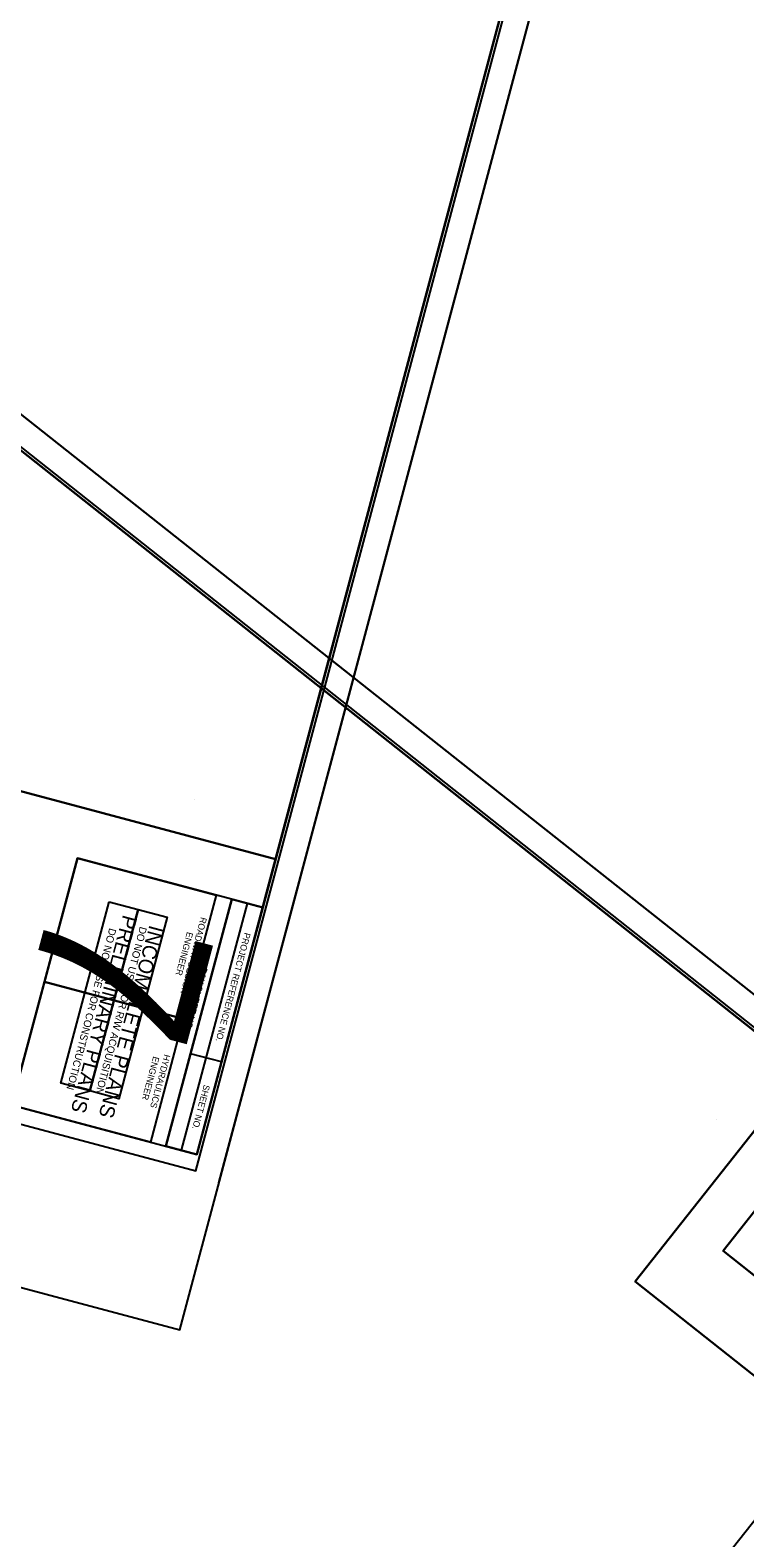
# Model space of a CAD drawing. Extents: x 1778994 to 1784559, y 810461 to 816654.
# Drawn here: x 1783094 to 1783653, y 813868 to 815048 of the extents above; entities that cross this region are included whole.
import ezdxf

# ---------------------------------------------------------------- set-up
doc = ezdxf.new("R2010")
doc.units = 0
for name, color, linetype in [('Sheet Clip Boundary CELL', 7, 'Continuous'), ('Sheet Cutting Line CELL', 7, 'Continuous'), ('Sheet Layout Plan Border', 7, 'Continuous'), ('Sheet North Arrow Point CELL', 7, 'Continuous'), ('Sheet Plan CELL', 7, 'Continuous'), ('Sheet Plan Layout CELL', 7, 'Continuous'), ('Sheet Plot Border Inside CELL', 7, 'Continuous'), ('Sheet Plot Border Outside CELL', 7, 'Continuous'), ('Sheet Sticker Incomplete CELL', 7, 'Continuous'), ('Sheet Sticker Preliminary CELL', 7, 'Continuous')]:
    doc.layers.add(name, color=color, linetype=linetype)

msp = doc.modelspace()

# ---------------------------------------------------------------- linework, layer by layer
at = {"layer": 'Sheet Clip Boundary CELL'}
for points in [[(1782583.3, 815839.3), (1782222.6, 814486.6), (1783032.8, 814270.5), (1783081.5, 814453.4), (1783285.9, 814398.9), (1783597.9, 815568.8)], [(1782097.5, 814162.5), (1783195.2, 813293.5), (1783715.7, 813950.9), (1783567.3, 814068.4), (1783698.6, 814234.2), (1782749.3, 814985.7)]]:
    msp.add_lwpolyline(points, close=True, dxfattribs=at)
at = {"layer": 'Sheet Cutting Line CELL'}
for p, q in [((1783241.6, 814145.5), (1783675.4, 815772.2)), ((1783913.4, 814092.8), (1782593.5, 815137.7))]:
    msp.add_line(p, q, dxfattribs=at)
at = {"layer": 'Sheet Layout Plan Border'}
for points in [[(1782583.3, 815839.3), (1782222.6, 814486.6), (1783032.8, 814270.5), (1783081.5, 814453.4), (1783285.9, 814398.9), (1783597.9, 815568.8)], [(1782097.5, 814162.5), (1783195.2, 813293.5), (1783715.7, 813950.9), (1783567.3, 814068.4), (1783698.6, 814234.2), (1782749.3, 814985.7)]]:
    msp.add_lwpolyline(points, close=True, dxfattribs=at)
at = {"layer": 'Sheet North Arrow Point CELL'}
for p, q in [((1783222.8, 814445.6), (1783222.8, 814445.6)), ((1783630.7, 814194.9), (1783630.7, 814194.9))]:
    msp.add_line(p, q, dxfattribs=at)
at = {"layer": 'Sheet Plan CELL'}
for p, q in [((1783251.6, 814367.5), (1783200, 814174.2)), ((1783251.6, 814367.5), (1783200, 814174.2)), ((1783263.7, 814364.3), (1783212.1, 814171)), ((1783251.6, 814367.5), (1783239.5, 814370.7)), ((1783213.7, 814274), (1783105, 814303)), ((1783243.5, 814240.2), (1783219.3, 814246.6))]:
    msp.add_line(p, q, dxfattribs=at)
for points in [[(1783224.2, 814167.7), (1783610.8, 815617.1), (1782596.2, 815887.7), (1782209.7, 814438.3)], [(1782596.2, 815887.7), (1783610.7, 815617.1), (1783275.8, 814361), (1783130.8, 814399.7), (1783079.2, 814206.4), (1782209.7, 814438.3)], [(1783886.2, 814085.7), (1782710.1, 815016.8), (1782058.3, 814193.5), (1783234.4, 813262.4)], [(1782058.3, 814193.5), (1782710.1, 815016.8), (1783729.3, 814209.9), (1783636.2, 814092.2), (1783793, 813968), (1783234.4, 813262.4)], [(1783239.5, 814370.7), (1783213.7, 814274), (1783105, 814303), (1783130.8, 814399.7)], [(1783275.8, 814361), (1783224.2, 814167.7), (1783200, 814174.2), (1783251.6, 814367.5)], [(1783213.7, 814274), (1783188, 814177.4), (1783079.2, 814206.4), (1783105, 814303)], [(1783706, 814180.4), (1783784.4, 814118.3), (1783714.6, 814030.1), (1783636.2, 814092.2)]]:
    msp.add_lwpolyline(points, close=True, dxfattribs=at)
at = {"layer": 'Sheet Plan Layout CELL'}
for points in [[(1783610.7, 815617.1), (1782596.2, 815887.7), (1782209.7, 814438.3), (1783019.9, 814222.2), (1783081.5, 814453.4), (1783285.9, 814398.9)], [(1782710.1, 815016.8), (1782058.3, 814193.5), (1783234.4, 813262.4), (1783754.9, 813919.9), (1783567.3, 814068.4), (1783698.6, 814234.2)], [(1783081.5, 814453.4), (1783019.9, 814222.2), (1783224.2, 814167.7), (1783285.9, 814398.9)], [(1783567.3, 814068.4), (1783754.9, 813919.9), (1783886.2, 814085.6), (1783698.6, 814234.2)]]:
    msp.add_lwpolyline(points, close=True, dxfattribs=at)
at = {"layer": 'Sheet Plot Border Inside CELL'}
for points in [[(1782633.3, 816036.6), (1782204.1, 814426.9), (1783223.4, 814155), (1783652.7, 815764.7)], [(1781936.4, 814286.8), (1783242.6, 813252.7), (1783897.5, 814079.9), (1782591.3, 815114)]]:
    msp.add_lwpolyline(points, close=True, dxfattribs=at)
at = {"layer": 'Sheet Plot Border Outside CELL'}
for points in [[(1782586.7, 815939.4), (1782152.9, 814312.8), (1783210.9, 814030.6), (1783644.8, 815657.3)], [(1781913.8, 814279.2), (1783233.7, 813234.2), (1783913.4, 814092.8), (1782593.5, 815137.7)]]:
    msp.add_lwpolyline(points, close=True, dxfattribs=at)
at = {"layer": 'Sheet Sticker Incomplete CELL'}
msp.add_lwpolyline([(1783178.3, 814359.5), (1783201, 814353.5), (1783163.1, 814211.4), (1783140.4, 814217.5)], close=True, dxfattribs=at)
at = {"layer": 'Sheet Sticker Preliminary CELL'}
msp.add_lwpolyline([(1783155.6, 814365.6), (1783178.3, 814359.5), (1783140.4, 814217.5), (1783117.7, 814223.6)], close=True, dxfattribs=at)

# ---------------------------------------------------------------- texts
at = {"layer": 'Sheet Plan CELL'}
for s, p in [('ROADWAY DESIGN', (1783227.4, 814353.9)), ('ENGINEER', (1783216.6, 814342.3)), ('PROJECT REFERENCE NO.', (1783261.6, 814341.8)), ('R/W SHEET NO.', (1783228, 814314.8)), ('HYDRAULICS', (1783198.8, 814246.5)), ('ENGINEER', (1783190.2, 814244.9)), ('SHEET NO.', (1783229.8, 814222.8))]:
    msp.add_text(s, height=5, rotation=255.0673, dxfattribs=at).set_placement(p)
at = {"layer": 'Sheet Plan Layout CELL'}
msp.add_text('7', height=131.3, rotation=255.0673, dxfattribs=at).set_placement((1783112.4, 814373.7))
at = {"layer": 'Sheet Sticker Incomplete CELL'}
for s, height, p in [('DO NOT USE FOR R/W ACQUISITION', 5.76, (1783179.7, 814346.5)), ('INCOMPLETE PLANS', 11.52, (1783187.3, 814347.9))]:
    msp.add_text(s, height=height, rotation=255.0673, dxfattribs=at).set_placement(p)
at = {"layer": 'Sheet Sticker Preliminary CELL'}
for s, height, p in [('PRELIMINARY PLANS', 11.52, (1783166.6, 814355.9)), ('DO NOT USE FOR CONSTRUCTION', 5.76, (1783155.8, 814345.3))]:
    msp.add_text(s, height=height, rotation=255.0673, dxfattribs=at).set_placement(p)

doc.saveas('drawing.dxf')
